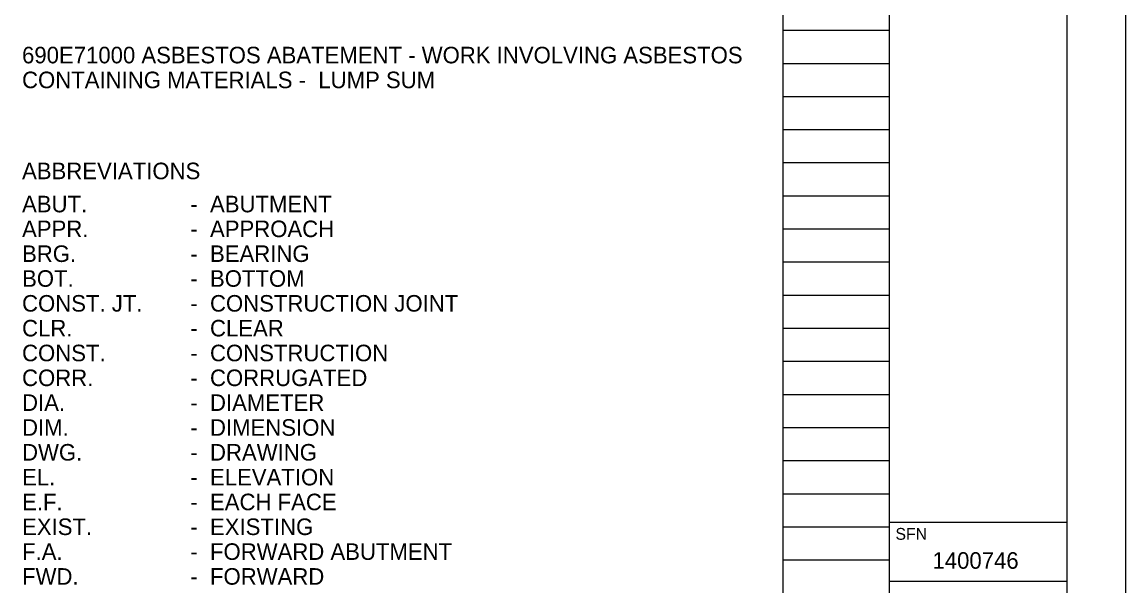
# Model space of a CAD drawing. Extents: x 0 to 34, y 0 to 22.
# Drawn here: x 24.66 to 34, y 4.96 to 9.73 of the extents above; entities that cross this region are included whole.
import ezdxf

# ---------------------------------------------------------------- set-up
doc = ezdxf.new("R2010")
doc.units = 0
for name, color, linetype in [('BR_P_Gen_Text', 7, 'Continuous'), ('SC_Scratch5', 7, 'Continuous'), ('SH_Border', 7, 'Continuous'), ('SH_Cut_Line', 7, 'Continuous'), ('SH_Data', 7, 'Continuous')]:
    doc.layers.add(name, color=color, linetype=linetype)

msp = doc.modelspace()

# ---------------------------------------------------------------- linework, layer by layer
at = {"layer": 'SC_Scratch5'}
for p, q in [((31.1, 0.98), (31.1, 21.14)), ((32, 0.98), (32, 21.14)), ((31.1, 9.66), (32, 9.66)), ((31.1, 9.38), (32, 9.38)), ((31.1, 9.1), (32, 9.1)), ((31.1, 8.82), (32, 8.82)), ((31.1, 8.54), (32, 8.54)), ((31.1, 8.26), (32, 8.26)), ((31.1, 7.98), (32, 7.98)), ((31.1, 7.7), (32, 7.7)), ((31.1, 7.42), (32, 7.42)), ((31.1, 7.14), (32, 7.14)), ((31.1, 6.86), (32, 6.86)), ((31.1, 6.58), (32, 6.58)), ((31.1, 6.3), (32, 6.3)), ((31.1, 6.02), (32, 6.02)), ((31.1, 5.74), (32, 5.74)), ((31.1, 5.46), (32, 5.46)), ((31.1, 5.18), (32, 5.18))]:
    msp.add_line(p, q, dxfattribs=at)
at = {"layer": 'SH_Border'}
for p, q in [((32, 0.5), (32, 21.5)), ((32, 5.5), (33.5, 5.5)), ((32, 5), (33.5, 5))]:
    msp.add_line(p, q, dxfattribs=at)
msp.add_lwpolyline([(1.5, 21.5), (33.5, 21.5), (33.5, 0.5), (1.5, 0.5)], close=True, dxfattribs=at)
at = {"layer": 'SH_Cut_Line'}
msp.add_lwpolyline([(0, 0), (34, 0), (34, 22), (0, 22)], close=True, dxfattribs=at)

# ---------------------------------------------------------------- texts
at = {"layer": 'BR_P_Gen_Text'}
for s, p in [('690E71000 ASBESTOS ABATEMENT - WORK INVOLVING ASBESTOS ', (24.66, 9.38)), ('CONTAINING MATERIALS -  LUMP SUM', (24.66, 9.17)), ('ABBREVIATIONS', (24.66, 8.4)), ('ABUT.', (24.66, 8.12)), ('-  ABUTMENT', (26.0838, 8.12)), ('APPR.', (24.66, 7.91)), ('-  APPROACH', (26.0838, 7.91)), ('BRG.', (24.66, 7.7)), ('-  BEARING', (26.0838, 7.7)), ('BOT.', (24.66, 7.49)), ('-  BOTTOM', (26.0838, 7.49)), ('CONST. JT.', (24.66, 7.28)), ('-  CONSTRUCTION JOINT', (26.0838, 7.28)), ('CLR.', (24.66, 7.07)), ('-  CLEAR', (26.0838, 7.07)), ('CONST.', (24.66, 6.86)), ('-  CONSTRUCTION', (26.0838, 6.86)), ('CORR.', (24.66, 6.65)), ('-  CORRUGATED', (26.0838, 6.65)), ('DIA.', (24.66, 6.44)), ('-  DIAMETER', (26.0838, 6.44)), ('DIM.', (24.66, 6.23)), ('-  DIMENSION', (26.0838, 6.23)), ('DWG.', (24.66, 6.02)), ('-  DRAWING', (26.0838, 6.02)), ('EL.', (24.66, 5.81)), ('-  ELEVATION', (26.0838, 5.81)), ('E.F.', (24.66, 5.6)), ('-  EACH FACE', (26.0838, 5.6)), ('EXIST.', (24.66, 5.39)), ('-  EXISTING', (26.0838, 5.39)), ('F.A.', (24.66, 5.18)), ('-  FORWARD ABUTMENT', (26.0838, 5.18)), ('FWD.', (24.66, 4.97)), ('-  FORWARD', (26.0838, 4.97))]:
    msp.add_text(s, height=0.14, dxfattribs=at).set_placement(p)
at = {"layer": 'SH_Data'}
for s, height, p in [('SFN', 0.1, (32.05, 5.35)), ('1400746', 0.14, (32.3633, 5.105))]:
    msp.add_text(s, height=height, dxfattribs=at).set_placement(p)

doc.saveas('drawing.dxf')
